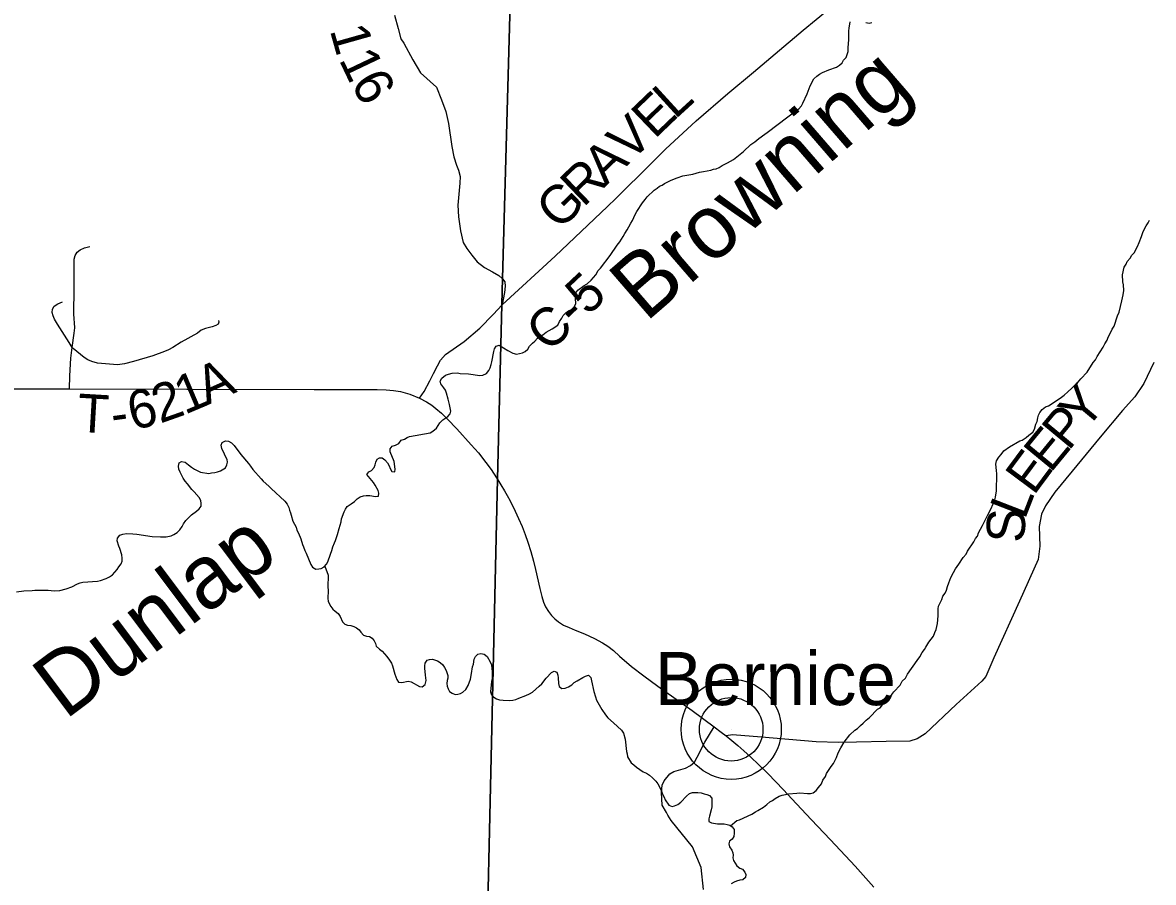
# Model space of a CAD drawing. Extents: x -14196 to 143, y -6096 to 28.
# Drawn here: x 61.569 to 63.25, y 21.69 to 22.967 of the extents above; entities that cross this region are included whole.
import ezdxf

# ---------------------------------------------------------------- set-up
doc = ezdxf.new("R2010")
doc.units = 0
for name, color, linetype in [('GM_X_Corporation', 7, 'Continuous'), ('GM_X_County_Road', 7, 'Continuous'), ('GM_X_County_Road_Text', 7, 'Continuous'), ('GM_X_Minor_River', 7, 'Continuous'), ('GM_X_Minor_River_Text', 7, 'Continuous'), ('GM_X_State_Route', 7, 'Continuous'), ('GM_X_Township_Road', 7, 'Continuous'), ('GM_X_Township_Road_Text', 7, 'Continuous'), ('GM_X_Unincorporated', 7, 'Continuous'), ('GM_X_Unincorporated_Location', 7, 'Continuous'), ('GM_X_Unincorporated_Text', 7, 'Continuous')]:
    doc.layers.add(name, color=color, linetype=linetype)

msp = doc.modelspace()

# ---------------------------------------------------------------- linework, layer by layer
at = {"layer": 'GM_X_Corporation'}
msp.add_lwpolyline([(62.1999, 18.7816), (62.2235, 19.866), (62.2323, 20.4208), (62.2487, 21.1358), (62.2751, 22.2884), (62.2815, 22.5484), (62.2824, 22.5866), (62.306, 23.4402), (61.9207, 23.4521), (60.7524, 23.485), (60.7179, 23.4857), (60.6994, 23.486), (60.6731, 23.4865), (60.4232, 23.4912), (60.4233, 23.5426), (60.4242, 23.5839), (60.4246, 23.6029), (60.4257, 23.6513), (60.4267, 23.6985), (58.1028, 23.6985), (58.1028, 18.8711)], dxfattribs=at)
msp.add_lwpolyline([(64.9028, 18.7286), (64.9028, 23.6985), (62.6174, 23.6985), (62.6129, 23.4358), (62.306, 23.4402), (62.2824, 22.5866), (62.2815, 22.5484), (62.2751, 22.2884), (62.2487, 21.1358), (62.2323, 20.4208), (62.2235, 19.866), (62.1999, 18.7816), (62.384, 18.775), (62.5403, 18.7731), (63.0887, 18.7577), (63.6879, 18.7414), (64.3696, 18.7343), (64.4266, 18.7347)], close=True, dxfattribs=at)
at = {"layer": 'GM_X_County_Road'}
for points in [[(62.4604, 22.7153), (62.4937, 22.7481), (62.5246, 22.7789), (62.5701, 22.8213), (62.6175, 22.8618), (62.6552, 22.8935), (62.6875, 22.9205), (62.729, 22.9557), (62.7873, 23.0039), (62.8755, 23.0769), (62.9203, 23.114), (62.9892, 23.1734), (63.0566, 23.2313), (63.0976, 23.2646), (63.1356, 23.2966), (63.1718, 23.3275), (63.1978, 23.348), (63.2125, 23.3615), (63.2192, 23.3699), (63.2259, 23.3844), (63.2292, 23.3947), (63.2351, 23.4066)], [(62.1592, 22.409), (62.1658, 22.419), (62.1746, 22.4346), (62.1798, 22.4457), (62.1858, 22.4569), (62.1902, 22.4653), (62.1978, 22.4738), (62.2255, 22.4931), (62.2489, 22.5131), (62.2685, 22.5333), (62.2817, 22.5479), (62.3607, 22.6202), (62.4385, 22.6938), (62.4507, 22.7058), (62.4604, 22.7153)]]:
    msp.add_lwpolyline(points, dxfattribs=at)
at = {"layer": 'GM_X_Minor_River'}
for points in [[(62.4973, 22.7083), (62.5078, 22.7179), (62.512, 22.7209), (62.5158, 22.724), (62.5195, 22.7256), (62.5233, 22.7279), (62.5328, 22.7329), (62.5419, 22.7364), (62.5502, 22.7392), (62.5651, 22.742), (62.5749, 22.7447), (62.581, 22.7459), (62.592, 22.7479), (62.5958, 22.7491), (62.6, 22.7499), (62.6042, 22.7515), (62.6087, 22.7546), (62.617, 22.7588), (62.6257, 22.7638), (62.6405, 22.7754), (62.6514, 22.7861), (62.6574, 22.79), (62.6631, 22.7946), (62.6722, 22.8011), (62.6759, 22.8035), (62.7062, 22.8269), (62.7103, 22.83), (62.7141, 22.8323), (62.7182, 22.8358), (62.7228, 22.8389), (62.7265, 22.8435), (62.7288, 22.8473), (62.7351, 22.861), (62.7396, 22.8732), (62.7452, 22.8836), (62.7493, 22.8874), (62.7535, 22.8905), (62.758, 22.8928), (62.7675, 22.8967), (62.7789, 22.901), (62.7834, 22.9037), (62.7872, 22.9071), (62.789, 22.9113), (62.7932, 22.9152), (62.7961, 22.9243), (62.7961, 22.9293), (62.7971, 22.9418), (62.7973, 22.9547), (62.7977, 22.9589), (62.7991, 22.9681)], [(62.8223, 22.9671), (62.8273, 22.9664), (62.8311, 22.9672)], [(62.0959, 22.3183), (62.0997, 22.3202), (62.1035, 22.3203), (62.1077, 22.3176), (62.1112, 22.3131), (62.1135, 22.3093), (62.1159, 22.3037), (62.1178, 22.2999), (62.1224, 22.2995), (62.1227, 22.3037), (62.1214, 22.3151), (62.1156, 22.3291), (62.1152, 22.3337), (62.1185, 22.3379), (62.1235, 22.3391), (62.1284, 22.3418), (62.1318, 22.3464), (62.1367, 22.3483), (62.1405, 22.3506), (62.1443, 22.3518), (62.1747, 22.3574), (62.1788, 22.3598), (62.1841, 22.3644), (62.189, 22.3724), (62.1935, 22.3766), (62.2011, 22.3816), (62.2048, 22.3855), (62.2056, 22.3896), (62.2036, 22.3995), (62.2024, 22.4033), (62.2016, 22.4075), (62.1992, 22.4166), (62.1976, 22.4207), (62.1953, 22.4245), (62.1907, 22.4302), (62.1899, 22.4343), (62.1921, 22.4385), (62.1974, 22.4432), (62.2019, 22.4447), (62.2076, 22.4459), (62.2153, 22.4464), (62.2194, 22.4456), (62.232, 22.445), (62.2488, 22.4429), (62.2533, 22.4433), (62.2587, 22.4456), (62.262, 22.4502), (62.2639, 22.4541), (62.2654, 22.459), (62.2665, 22.4632), (62.2694, 22.4784), (62.2705, 22.4822), (62.2731, 22.4864), (62.2776, 22.4876), (62.2903, 22.4798), (62.2979, 22.476), (62.3033, 22.4746), (62.312, 22.4762), (62.3158, 22.4785), (62.3199, 22.482), (62.3226, 22.4865), (62.3267, 22.4908), (62.3305, 22.4938), (62.3346, 22.4981), (62.3422, 22.5031), (62.3471, 22.5069), (62.3562, 22.5119), (62.3645, 22.5173), (62.3671, 22.5227), (62.3705, 22.5277), (62.3727, 22.5319), (62.3765, 22.5357), (62.3806, 22.5388), (62.3848, 22.5407), (62.3889, 22.5449), (62.3912, 22.5491), (62.3907, 22.5575), (62.3899, 22.5613), (62.3914, 22.5655), (62.3944, 22.5693), (62.4035, 22.5766), (62.408, 22.5789), (62.414, 22.5843), (62.4178, 22.5882), (62.4212, 22.5924), (62.4246, 22.5985), (62.4279, 22.6023), (62.4422, 22.6211), (62.4527, 22.6364), (62.4568, 22.6414), (62.4617, 22.649), (62.464, 22.6536), (62.4677, 22.6593), (62.4703, 22.6635), (62.4729, 22.6689), (62.4755, 22.6731), (62.4793, 22.6819), (62.4819, 22.6864), (62.4905, 22.6994), (62.4946, 22.7044), (62.4973, 22.7083)], [(63.051, 22.3454), (63.0548, 22.3465), (63.0605, 22.3504), (63.0646, 22.3542), (63.0707, 22.3585), (63.0729, 22.3631), (63.0751, 22.3703), (63.077, 22.3741), (63.0781, 22.3798), (63.0792, 22.3836), (63.0811, 22.3878), (63.0844, 22.392), (63.0893, 22.3959), (63.0939, 22.3975), (63.0992, 22.4013), (63.1132, 22.4106), (63.1173, 22.4136), (63.1226, 22.4186), (63.1286, 22.424), (63.1328, 22.4282), (63.1369, 22.4317), (63.1418, 22.4378), (63.1512, 22.4474), (63.1602, 22.4619), (63.1636, 22.4661), (63.1662, 22.4707), (63.1752, 22.4849), (63.1774, 22.4898), (63.1808, 22.4952), (63.1827, 22.4998), (63.1849, 22.504), (63.1883, 22.5116), (63.1913, 22.5158), (63.1964, 22.5311), (63.199, 22.5368), (63.203, 22.5536), (63.2049, 22.5627), (63.2056, 22.5688), (63.2055, 22.5775), (63.2043, 22.5817), (63.2038, 22.5923), (63.2063, 22.6034), (63.2093, 22.6083), (63.2108, 22.6122), (63.215, 22.6168), (63.2176, 22.6213), (63.2213, 22.6248), (63.2262, 22.6343), (63.2284, 22.6404), (63.2321, 22.6492), (63.2347, 22.6565), (63.2388, 22.6649), (63.2422, 22.6695), (63.2441, 22.6733)], [(61.8344, 22.2485), (61.8347, 22.2523), (61.8339, 22.2569), (61.8316, 22.2614), (61.8243, 22.2697), (61.8208, 22.2735), (61.8142, 22.2818), (61.8108, 22.2855), (61.8077, 22.2901), (61.8034, 22.2988), (61.8015, 22.3037), (61.8006, 22.3082), (61.8017, 22.3128), (61.8055, 22.3151), (61.8105, 22.3137), (61.8159, 22.3099), (61.8201, 22.3065), (61.8247, 22.3035), (61.8285, 22.3013), (61.8335, 22.2991), (61.8461, 22.2973), (61.8499, 22.2981), (61.8548, 22.2985), (61.859, 22.2993), (61.8631, 22.3009), (61.8707, 22.3055), (61.8729, 22.3101), (61.8737, 22.3139), (61.8732, 22.3177), (61.8713, 22.3215), (61.8694, 22.326), (61.8651, 22.3343), (61.8643, 22.3392), (61.8658, 22.3431), (61.8707, 22.3458), (61.8752, 22.3451), (61.8798, 22.3424), (61.8837, 22.3387), (61.8933, 22.3255), (61.9049, 22.3119), (61.9076, 22.3081), (61.9115, 22.3028), (61.9238, 22.2893), (61.9265, 22.2855), (61.9353, 22.2784), (61.9384, 22.2746), (61.9588, 22.2558), (61.9622, 22.2513), (61.9646, 22.2467), (61.9658, 22.2426), (61.9673, 22.2388), (61.9681, 22.235), (61.9709, 22.2263), (61.9755, 22.2172), (61.9767, 22.213), (61.979, 22.2085), (61.9826, 22.1998), (61.9849, 22.1918), (61.9865, 22.188), (61.9885, 22.1827), (61.9908, 22.1786), (61.9974, 22.1619), (62.0001, 22.1581), (62.0047, 22.1551), (62.0093, 22.1552), (62.0131, 22.156), (62.0172, 22.1583), (62.0206, 22.1621), (62.0229, 22.166), (62.0266, 22.1774), (62.0288, 22.1827), (62.0303, 22.1881), (62.0329, 22.1938), (62.034, 22.1976), (62.0373, 22.2064), (62.0395, 22.2155), (62.0424, 22.2254), (62.0432, 22.2296), (62.0469, 22.2399), (62.0491, 22.2441), (62.0517, 22.2479), (62.0574, 22.2518), (62.0623, 22.2556), (62.0665, 22.2595), (62.071, 22.2622), (62.0759, 22.2638), (62.0797, 22.2642), (62.0851, 22.2642), (62.0934, 22.2628), (62.098, 22.2636), (62.0987, 22.2678), (62.0975, 22.2716), (62.0933, 22.2799), (62.0906, 22.2837), (62.0809, 22.2957), (62.0835, 22.2995), (62.0877, 22.3015), (62.0915, 22.3061), (62.093, 22.3099), (62.0941, 22.3141), (62.0959, 22.3183)], [(62.6213, 21.7737), (62.6306, 21.7815), (62.6347, 21.7827), (62.6529, 21.7909), (62.6582, 21.7944), (62.662, 21.7963), (62.6703, 21.8013), (62.6752, 21.8052), (62.6797, 21.8094), (62.6835, 21.8113), (62.6877, 21.8144), (62.6937, 21.8175), (62.6979, 21.8191), (62.7029, 21.8199), (62.7074, 21.821), (62.7196, 21.8223), (62.7245, 21.8224), (62.7356, 21.8217), (62.7401, 21.8217), (62.7443, 21.8225), (62.7485, 21.826), (62.7518, 21.8306), (62.7564, 21.836), (62.7586, 21.8413), (62.7623, 21.8467), (62.7638, 21.8512), (62.7709, 21.8619), (62.7743, 21.8662), (62.7788, 21.8753), (62.781, 21.8822), (62.7851, 21.8894), (62.7904, 21.8979), (62.7986, 21.9086), (62.8058, 21.9159), (62.8099, 21.9182), (62.8145, 21.9228), (62.8186, 21.9262), (62.8231, 21.9308), (62.8277, 21.9347), (62.8397, 21.947), (62.8435, 21.9489), (62.8469, 21.9535), (62.8529, 21.9593), (62.857, 21.965), (62.8608, 21.9685), (62.8638, 21.9727), (62.8732, 21.9826), (62.8766, 21.9884), (62.8811, 21.993), (62.8845, 21.9987), (62.8987, 22.019), (62.9025, 22.0247), (62.9062, 22.0312), (62.9096, 22.0354), (62.9115, 22.0392), (62.916, 22.0465), (62.9227, 22.0553), (62.9249, 22.0607), (62.9268, 22.0652), (62.929, 22.0744), (62.93, 22.0854), (62.9299, 22.096), (62.9306, 22.0999), (62.9321, 22.104), (62.9355, 22.1098), (62.9369, 22.1147), (62.9403, 22.1193), (62.9422, 22.1235), (62.9436, 22.1292), (62.9455, 22.1346), (62.9474, 22.1384), (62.9488, 22.1426), (62.9526, 22.1502), (62.9556, 22.1552), (62.9608, 22.1625), (62.9672, 22.1724), (62.9713, 22.177), (62.9736, 22.1816), (62.9829, 22.1954), (62.9855, 22.2003), (62.9882, 22.2041), (62.99, 22.2087), (62.993, 22.2145), (62.9956, 22.2198), (63.0031, 22.2347), (63.0087, 22.245), (63.0109, 22.2511), (63.0135, 22.2561), (63.015, 22.2618), (63.0168, 22.2713), (63.0167, 22.277), (63.0173, 22.2907), (63.0169, 22.2968), (63.0165, 22.3017), (63.0156, 22.3108), (63.0167, 22.3158), (63.0201, 22.3215), (63.0235, 22.3253), (63.0276, 22.3307), (63.0359, 22.3369), (63.051, 22.3454)], [(61.5601, 22.1212), (61.5708, 22.1229), (61.5833, 22.1234), (61.5871, 22.1238), (61.5928, 22.1238), (61.597, 22.1235), (61.6073, 22.1236), (61.6161, 22.1229), (61.6244, 22.123), (61.6339, 22.1258), (61.6423, 22.1289), (61.6506, 22.1331), (61.6548, 22.1347), (61.6586, 22.1355), (61.6806, 22.1372), (61.6848, 22.138), (61.6931, 22.1411), (61.6981, 22.1435), (61.7026, 22.1465), (61.7064, 22.1504), (61.7097, 22.1546), (61.712, 22.1584), (61.7154, 22.1626), (61.7172, 22.1668), (61.7172, 22.1714), (61.7164, 22.1763), (61.7136, 22.1854), (61.712, 22.1892), (61.7097, 22.1968), (61.7104, 22.201), (61.7134, 22.2052), (61.718, 22.2071), (61.7233, 22.2079), (61.7328, 22.2076), (61.7389, 22.2069), (61.7618, 22.2037), (61.7743, 22.2031), (61.7823, 22.2032), (61.7899, 22.2044), (61.7941, 22.2063), (61.799, 22.2094), (61.8028, 22.2133), (61.8065, 22.2182), (61.8084, 22.2224), (61.8118, 22.227), (61.8155, 22.2312), (61.82, 22.2355), (61.8276, 22.2412), (61.8314, 22.2447), (61.8344, 22.2485)], [(62.0182, 22.1594), (62.0235, 22.1462), (62.0235, 22.1416), (62.0228, 22.1325), (62.0234, 22.1192), (62.0226, 22.1154), (62.0227, 22.1116), (62.0235, 22.1071), (62.0274, 22.0995), (62.0301, 22.0953), (62.0339, 22.0923), (62.0381, 22.089), (62.0412, 22.0848), (62.0444, 22.0769), (62.0482, 22.0731), (62.052, 22.0716), (62.057, 22.0713), (62.0616, 22.0698), (62.0654, 22.0679), (62.0692, 22.0649), (62.0719, 22.0612), (62.0758, 22.057), (62.0804, 22.0552), (62.0849, 22.0548), (62.0888, 22.0522), (62.0915, 22.0484), (62.0934, 22.0443), (62.0946, 22.0405), (62.0996, 22.036), (62.1034, 22.0333), (62.1104, 22.0254), (62.1146, 22.0198), (62.1173, 22.0152), (62.1189, 22.0115), (62.1221, 21.9989), (62.1252, 21.991), (62.1279, 21.9872), (62.1328, 21.9865), (62.142, 21.9885), (62.1465, 21.9874), (62.1588, 21.9807), (62.163, 21.98), (62.1675, 21.9838), (62.169, 21.9895), (62.1685, 21.9937), (62.1677, 21.9975), (62.1669, 22.0077), (62.1668, 22.0115), (62.1672, 22.0153), (62.1702, 22.0195), (62.174, 22.0207), (62.1782, 22.0211), (62.1858, 22.0186), (62.1896, 22.0163), (62.1935, 22.0126), (62.1962, 22.0088), (62.1985, 22.0046), (62.2009, 21.997), (62.2009, 21.9932), (62.2002, 21.9894), (62.1998, 21.9849), (62.1999, 21.9811), (62.2014, 21.9773), (62.2038, 21.9731), (62.2076, 21.9705), (62.2118, 21.9686), (62.216, 21.9691), (62.2198, 21.9702), (62.2236, 21.9722), (62.2277, 21.976), (62.2315, 21.9821), (62.2348, 21.9917), (62.2362, 22), (62.2377, 22.0096), (62.2391, 22.0138), (62.2402, 22.0214), (62.2421, 22.0252), (62.2458, 22.0286), (62.25, 22.0298), (62.255, 22.0287), (62.2596, 22.0254), (62.2642, 22.017), (62.2658, 22.0129), (62.267, 22.0026), (62.2671, 21.9988), (62.2668, 21.9924), (62.266, 21.9882), (62.2647, 21.9726), (62.2659, 21.9684), (62.2693, 21.9646), (62.2732, 21.9624), (62.2777, 21.9609), (62.2835, 21.9602), (62.293, 21.9599), (62.2975, 21.9604), (62.3021, 21.9615), (62.3066, 21.9631), (62.3169, 21.967), (62.3226, 21.9697), (62.3267, 21.9724), (62.3369, 21.9809)], [(62.3369, 21.9809), (62.3407, 21.9847), (62.3474, 21.9931), (62.3554, 22.0016), (62.3591, 22.0035), (62.3633, 22.0017), (62.3645, 21.9975), (62.365, 21.9937), (62.3654, 21.985), (62.3666, 21.9808), (62.3704, 21.9778), (62.3754, 21.9782), (62.3803, 21.9802), (62.3852, 21.9832), (62.389, 21.9867), (62.3935, 21.989), (62.4019, 21.994), (62.4057, 21.996), (62.4102, 21.9975), (62.4137, 21.9938), (62.4145, 21.9888), (62.4181, 21.9733), (62.4208, 21.965), (62.422, 21.9604), (62.4298, 21.9464), (62.4352, 21.9385), (62.439, 21.934), (62.4471, 21.9265), (62.4594, 21.9159), (62.4621, 21.911), (62.4649, 21.9023), (62.4666, 21.8841), (62.4678, 21.8803), (62.4682, 21.8761), (62.4736, 21.8674), (62.4774, 21.8644), (62.4813, 21.8607), (62.4916, 21.8539), (62.4962, 21.8517), (62.5008, 21.8487), (62.5054, 21.8449), (62.51, 21.84), (62.5131, 21.8359), (62.5162, 21.8306), (62.5186, 21.8253), (62.5201, 21.8204), (62.5225, 21.8162), (62.524, 21.8121), (62.5298, 21.8045), (62.5344, 21.8023), (62.5382, 21.8031), (62.5428, 21.8054), (62.5473, 21.8089), (62.5556, 21.8177), (62.5605, 21.8215), (62.5647, 21.8231), (62.5726, 21.8232), (62.5776, 21.8225), (62.5822, 21.821), (62.586, 21.8203), (62.5898, 21.8188), (62.5933, 21.8146), (62.5937, 21.8097), (62.5934, 21.8017), (62.5927, 21.7971), (62.5898, 21.788), (62.589, 21.7842), (62.5891, 21.78), (62.5929, 21.7778), (62.6021, 21.7763), (62.6116, 21.7764), (62.6161, 21.7757), (62.62, 21.7746), (62.6238, 21.772), (62.6265, 21.7682), (62.6269, 21.7625), (62.6262, 21.7576), (62.6236, 21.7537), (62.6198, 21.7507), (62.6187, 21.7468), (62.6195, 21.7423), (62.623, 21.7374), (62.6246, 21.7336), (62.625, 21.7298), (62.6247, 21.726), (62.6255, 21.7222), (62.6305, 21.7139), (62.6351, 21.7109), (62.6393, 21.709), (62.6424, 21.7049), (62.6439, 21.7011), (62.6436, 21.6969), (62.6395, 21.6931), (62.6353, 21.6927), (62.6303, 21.6915), (62.6266, 21.6899), (62.622, 21.6872)]]:
    msp.add_lwpolyline(points, dxfattribs=at)
at = {"layer": 'GM_X_State_Route'}
for points in [[(61.505, 22.4228), (61.6388, 22.4229), (61.813, 22.4224), (62.0025, 22.4221), (62.0963, 22.4221), (62.1094, 22.4216), (62.1203, 22.4206), (62.1306, 22.4188), (62.1446, 22.4147), (62.1592, 22.409)], [(62.1592, 22.409), (62.1694, 22.4037), (62.1772, 22.3984), (62.1835, 22.3937), (62.1918, 22.3867), (62.2006, 22.378), (62.2144, 22.3636), (62.236, 22.3399), (62.2465, 22.3278), (62.2576, 22.3136), (62.2655, 22.3029), (62.2735, 22.2908), (62.2753, 22.2878), (62.2801, 22.2802), (62.2855, 22.2714), (62.2912, 22.2609)], [(62.2912, 22.2609), (62.2917, 22.26), (62.2967, 22.2504), (62.3014, 22.2411), (62.3062, 22.23), (62.3115, 22.2181), (62.3159, 22.2066), (62.3201, 22.1949), (62.3245, 22.1811), (62.3284, 22.167), (62.3314, 22.1545), (62.3376, 22.1261), (62.3406, 22.1141), (62.3433, 22.106), (62.3465, 22.099), (62.3506, 22.0921), (62.355, 22.0862), (62.3602, 22.0811), (62.3656, 22.0765), (62.3731, 22.0718), (62.3813, 22.068), (62.3904, 22.0644), (62.404, 22.0586), (62.419, 22.0518), (62.4309, 22.0457), (62.4387, 22.0405), (62.4471, 22.0339), (62.4564, 22.0256), (62.4741, 22.0101), (62.4922, 21.9962), (62.5131, 21.9811), (62.564, 21.9448), (62.5971, 21.9207), (62.6075, 21.9128), (62.6147, 21.9073), (62.6233, 21.9004), (62.6322, 21.8928), (62.6412, 21.8851), (62.6514, 21.8758), (62.6628, 21.8649), (62.6768, 21.8512), (62.7, 21.8268), (62.7122, 21.8138), (62.741, 21.7832), (62.7696, 21.753), (62.8063, 21.7138), (62.8186, 21.7005), (62.8342, 21.6825)]]:
    msp.add_lwpolyline(points, dxfattribs=at)
at = {"layer": 'GM_X_Township_Road'}
for points in [[(62.1216, 22.9779), (62.1272, 22.9582), (62.1312, 22.9427), (62.1355, 22.9363), (62.1491, 22.9117), (62.1604, 22.8925), (62.1843, 22.8709), (62.1919, 22.8523), (62.1982, 22.8348), (62.2021, 22.817), (62.2071, 22.7829), (62.2101, 22.7677), (62.2139, 22.7554), (62.2169, 22.7477), (62.2193, 22.7384), (62.219, 22.7286), (62.2162, 22.6957), (62.2169, 22.6782), (62.2198, 22.6575), (62.2241, 22.6405), (62.2294, 22.6312), (62.2369, 22.6215), (62.2446, 22.6117), (62.2557, 22.6029), (62.2673, 22.5965), (62.2769, 22.5912), (62.282, 22.5869), (62.2826, 22.5861), (62.2857, 22.5818), (62.2865, 22.5755), (62.2853, 22.5662), (62.2817, 22.5479)], [(61.6388, 22.4229), (61.6393, 22.4424), (61.6409, 22.4682), (61.6428, 22.4843), (61.646, 22.5054), (61.6466, 22.5134), (61.6461, 22.5207), (61.6457, 22.5271), (61.6451, 22.5342), (61.6451, 22.542), (61.6457, 22.5636), (61.6458, 22.6069), (61.646, 22.6154), (61.6472, 22.6209), (61.6501, 22.6259), (61.6547, 22.6296), (61.6613, 22.6325), (61.6689, 22.6345)], [(61.6443, 22.483), (61.6428, 22.4843), (61.6383, 22.4915), (61.621, 22.5188), (61.6167, 22.5262), (61.6144, 22.5313), (61.6129, 22.5364), (61.6135, 22.5413), (61.6159, 22.5456), (61.6216, 22.5492), (61.6284, 22.5523)], [(61.8605, 22.5246), (61.8607, 22.5217), (61.8596, 22.519), (61.8564, 22.5171), (61.8507, 22.515), (61.841, 22.5124), (61.8345, 22.51), (61.8292, 22.5055), (61.8048, 22.4921), (61.7922, 22.4844), (61.786, 22.4809), (61.78, 22.4782), (61.7626, 22.4719), (61.7339, 22.4636), (61.7204, 22.46), (61.7102, 22.4585), (61.6806, 22.4609), (61.6722, 22.4633), (61.6661, 22.4658), (61.6607, 22.4695), (61.6443, 22.483)], [(63.2502, 22.4621), (63.2354, 22.4307), (63.222, 22.4112), (63.2036, 22.3908), (63.1706, 22.3512), (63.129, 22.3005), (63.1035, 22.2694), (63.0893, 22.249), (63.0834, 22.2368), (63.0798, 22.2185), (63.0809, 22.1893), (63.0785, 22.1691), (63.0508, 22.1076), (63.0127, 22.0231), (63.0008, 21.9956), (62.9948, 21.9883), (62.9568, 21.9536), (62.9106, 21.9105), (62.8988, 21.903), (62.8877, 21.8995), (62.8524, 21.899), (62.8086, 21.8977), (62.7818, 21.8975), (62.7487, 21.8985), (62.6671, 21.9051), (62.6242, 21.9088), (62.6147, 21.9073)], [(62.5282, 21.7896), (62.5261, 21.7932), (62.5199, 21.8041), (62.5189, 21.8231), (62.5197, 21.834), (62.5228, 21.8403), (62.5311, 21.8506), (62.5369, 21.8542), (62.5544, 21.8592), (62.562, 21.863), (62.5678, 21.8684), (62.5718, 21.8754), (62.583, 21.898), (62.5971, 21.9207)], [(62.5813, 21.6788), (62.5778, 21.7118), (62.5645, 21.7424), (62.5328, 21.7815), (62.5282, 21.7896)]]:
    msp.add_lwpolyline(points, dxfattribs=at)
at = {"layer": 'GM_X_Unincorporated'}
for radius in [0.0744, 0.0472]:
    msp.add_circle((62.6223, 21.917), radius, dxfattribs=at)
at = {"layer": 'GM_X_Unincorporated_Location'}
msp.add_line((62.6223, 21.917), (62.6223, 21.917), dxfattribs=at)

# ---------------------------------------------------------------- texts
at = {"layer": 'GM_X_County_Road_Text'}
for s, height, rotation, p in [('L', 0.0568, 42.4233, (62.5386, 22.8222)), ('E', 0.0568, 43.7363, (62.5082, 22.793)), ('V', 0.0568, 43.8337, (62.4721, 22.7584)), ('A', 0.0568, 43.8357, (62.436, 22.7238)), ('R', 0.0568, 43.837, (62.4024, 22.6915)), ('G', 0.0568, 43.8331, (62.3663, 22.6568)), ('C-5', 0.05682, 43.3815, (62.351, 22.4753))]:
    msp.add_text(s, height=height, rotation=rotation, dxfattribs=at).set_placement(p)
at = {"layer": 'GM_X_Minor_River_Text'}
for s, height, rotation, p in [('Browning', 0.0947, 40.8592, (62.4951, 22.5207)), ('Dunlap', 0.09469, 36.8574, (61.6322, 21.93))]:
    msp.add_text(s, height=height, rotation=rotation, dxfattribs=at).set_placement(p)
at = {"layer": 'GM_X_Township_Road_Text'}
for s, rotation, p in [('1', 285.7342, (62.0254, 22.9561)), ('1', 295.471, (62.0386, 22.9125)), ('6', 299.8025, (62.0558, 22.8768)), ('A', 23.8851, (61.843, 22.3981)), ('1', 22.9047, (61.8098, 22.384)), ('6', 12.8101, (61.7323, 22.3612)), ('2', 19.582, (61.7734, 22.371)), ('Y', 50.1636, (63.148, 22.3589)), ('T', 356.6466, (61.6493, 22.3592)), ('P', 50.3903, (63.1236, 22.3294)), ('-', 7.5991, (61.7036, 22.3571)), ('E', 50.545, (63.0967, 22.2966)), ('E', 53.3787, (63.0718, 22.2631)), ('L', 68.813, (63.0584, 22.227)), ('S', 88.4603, (63.0583, 22.1937))]:
    msp.add_text(s, height=0.0568, rotation=rotation, dxfattribs=at).set_placement(p)
at = {"layer": 'GM_X_Unincorporated_Text'}
msp.add_text('Bernice', height=0.07898, rotation=0, dxfattribs=at).set_placement((62.509, 21.9529))

doc.saveas('drawing.dxf')
